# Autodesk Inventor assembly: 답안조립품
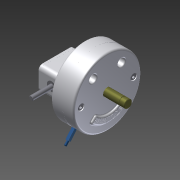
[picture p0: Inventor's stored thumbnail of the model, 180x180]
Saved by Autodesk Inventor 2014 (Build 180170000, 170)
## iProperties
Created: 2015-04
Part Number: 답안조립품
Document SubType Name: Assembly
Designer: Administrator
Mass: 3964.98 g
Surface Area: 3333.7 cm^2
Volume: 1140.85 cm^3
Density: 3.47546 g/cm^3
Author: Administrator
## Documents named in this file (15)
- C:\Documents and Settings\Administrator\바탕 화면\350406V1020\답안조립품.iam
- C:\Documents and Settings\Administrator\바탕 화면\350406V1020\본체.ipt
- C:\Documents and Settings\Administrator\바탕 화면\350406V1020\커버.ipt
- C:\Documents and Settings\Administrator\바탕 화면\350406V1020\커버2.ipt
- C:\Documents and Settings\Administrator\바탕 화면\350406V1020\M 10 x 35.ipt
- C:\Documents and Settings\Administrator\바탕 화면\350406V1020\M 5 x 12.ipt
- C:\Documents and Settings\Administrator\바탕 화면\350406V1020\부시.ipt
- C:\Documents and Settings\Administrator\바탕 화면\350406V1020\베어링62_22.ipt
- C:\Documents and Settings\Administrator\바탕 화면\350406V1020\축.ipt
- C:\Documents and Settings\Administrator\바탕 화면\350406V1020\멈춤링.ipt
- C:\Documents and Settings\Administrator\바탕 화면\350406V1020\가변 스프링.ipt
- C:\Documents and Settings\Administrator\바탕 화면\350406V1020\슬라이더2.ipt
- C:\Documents and Settings\Administrator\바탕 화면\350406V1020\슬라이더.ipt
- C:\Documents and Settings\Administrator\바탕 화면\350406V1020\평행핀.ipt
- C:\Documents and Settings\Administrator\바탕 화면\350406V1020\슬라이더3.ipt
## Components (6 placed, 4 different names)
1. M 10 x 35:1
2. M 10 x 35:2
3. M 5 x 12:1
4. M 5 x 12:2
5. KS B 1320 B B 5 x  20:1 — 플러쉬:2
6. 가변 스프링:1
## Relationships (1: Flush 1)
- 플러쉬:2 [Flush]: KS B 1320 B B 5 x  20:1
